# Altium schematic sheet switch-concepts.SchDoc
size B
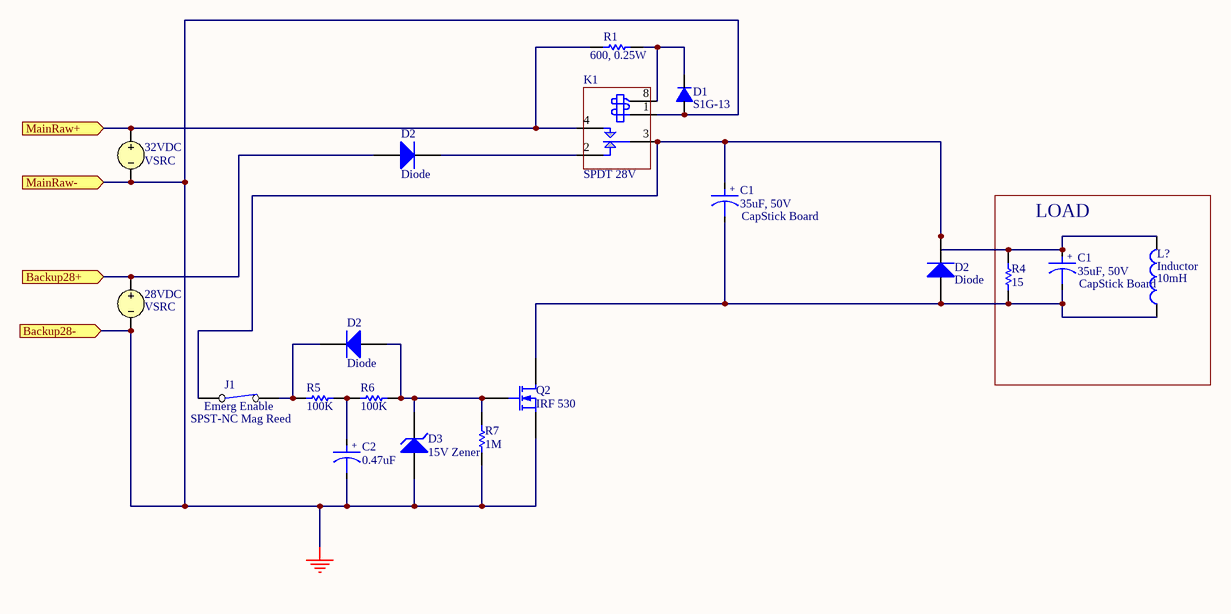
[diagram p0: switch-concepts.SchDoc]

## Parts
(Parts that share a designator on the sheet are numbered #1, #2 ... from top to bottom, then left to right.)
28VDC  VSRC
32VDC  VSRC
C1#1  35uF, 50V  DescSheet: CapStick Board
C1#2  35uF, 50V  DescSheet: CapStick Board
C2  0.47uF
D1  S1G-13  [SMA]
D2#1  Diode  [DSO-C2/X3.3]
D2#2  Diode  [DSO-C2/X3.3]
D2#3  Diode  [DSO-C2/X3.3]
D3  15V Zener  [DIODE-0.7]
J1  Emerg Enable  DescSheet: SPST-NC Mag Reed  [CGRID2]
K1  SPDT 28V  [NAIS-LZ]
L?  Inductor  value 10mH  [C1005-0402]
Q2  IRF 530  [BCY-W3/H.8]
R1  600, 0.25W  [AXIAL-0.3]
R4  15  [AXIAL-0.3]
R5  100K  [AXIAL-0.3]
R6  100K  [AXIAL-0.3]
R7  1M  [AXIAL-0.3]

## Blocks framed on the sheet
LOAD: C1#2 L? R4

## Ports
Backup28+ (in), Backup28- (in), MainRaw+ (in), MainRaw- (in)

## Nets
GND: 28VDC.2 32VDC.2 C2.2 D1.1(K) D3.1(A) K1.1(COIL+) Q2.3(S) R7.2 ; port Backup28-, port MainRaw-
Backup28+: 28VDC.1 D2#1.1(A) ; port Backup28+
MainRaw+: 32VDC.1 K1.4(NO) R1.2 ; port MainRaw+
NetC1#1_1: C1#1.1 C1#2.1 D2#2.2(K) J1.1(COMMON) K1.3(COMMON) L?.2 R4.2
NetC1#1_2: C1#1.2 C1#2.2 D2#2.1(A) L?.1 Q2.1(D) R4.1
NetC2_1: C2.1 R5.1 R6.2
NetD1_2: D1.2(A) K1.8(COIL-) R1.1
NetD2#1_2: D2#1.2(K) K1.2(NC)
NetD2#3_1: D2#3.1(A) D3.2(K) Q2.2(G) R6.1 R7.1
NetD2#3_2: D2#3.2(K) J1.2(NO) R5.2

Not connected (* = marked no-connect by the designer): K1 5(NO) 6(COMMON) 7(NC)

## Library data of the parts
28VDC 32VDC = VSRC: Voltage Source; Manufacturer: Generic Components; Class: Simulation; Note: PCB Footprint - Not required
C1#1 C1#2 C2 = CAPACITOR POL: Capacitor
D1 = DIODE_S: Diode; Manufacturer: Diodes Inc; VendorPartNo: S1GDICT-ND; Cost/ea: 0.288; DescSheet: 1A, 400V; Reference: T033, 578; Vendor: Digi-Key
D2#1-D2#3 = Diode: Default Diode; Manufacturer: Generic Components; Class: Discrete; SubClass: Diode - Switching
D3 = D Zener: Zener Diode; Manufacturer: Generic Components; Class: Discrete; SubClass: Diode - Zener
J1 = SW-SPST-NC
K1 = RELAY-NAIS-LZ-SPDT: Nais LZ Relay SPDT; ManufPartNo: ALZ12F24; VendorPartNo: 255-1447-ND; Cost/ea: 2.16; Reference: T033, 942; Vendor: Digi-Key
L? = Inductor: Manufacturer: Generic Components; Class: Passive
Q2 = MOSFET-N: N-Channel MOSFET; Manufacturer: Generic Components; Class: Discrete; SubClass: MOSFET - Low Power
R1 = Res1: Resistor; Manufacturer: Generic Components; Class: Passive; Value: 15
R4-R7 = Res1: Resistor; Manufacturer: Generic Components; Class: Passive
